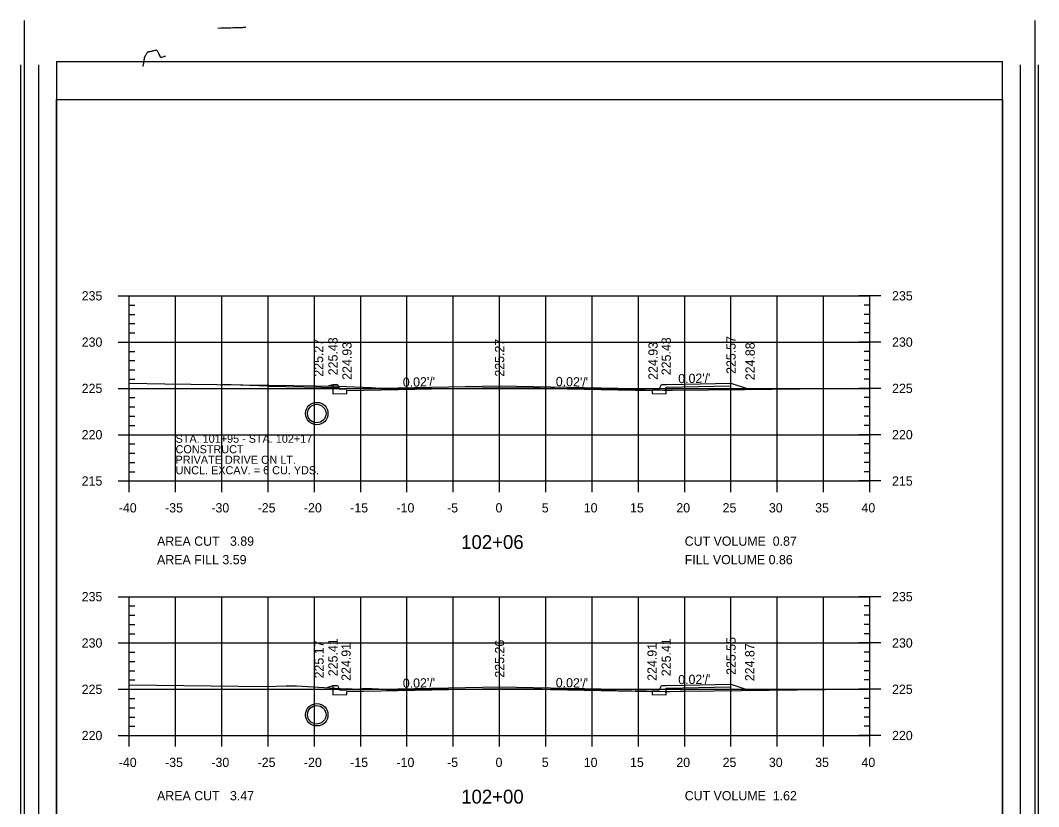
# Model space of a CAD drawing. Extents: x 1367903 to 1373764, y 376865 to 382130.
# Drawn here: x 1369975.7 to 1370195.7, y 377450.5 to 377620.4 of the extents above; entities that cross this region are included whole.
import ezdxf

# ---------------------------------------------------------------- set-up
doc = ezdxf.new("R2010")
doc.units = 0
for name, color, linetype in [('R_Axis', 7, 'Continuous'), ('R_Axis Annot', 7, 'Continuous'), ('R_Border', 7, 'Continuous'), ('R_Border PE', 7, 'Continuous'), ('R_Draft', 7, 'Continuous'), ('R_Drive', 7, 'Continuous'), ('R_Exist Surface', 7, 'Continuous'), ('R_Fin Surface', 7, 'Continuous'), ('R_Fin Surface Annot', 7, 'Continuous'), ('R_Grid', 7, 'Continuous'), ('R_Water', 7, 'Continuous')]:
    doc.layers.add(name, color=color, linetype=linetype)

msp = doc.modelspace()

# ---------------------------------------------------------------- linework, layer by layer
for points in [[(1370043.22, 377541.69), (1370043.22, 377541.03), (1370043.22, 377541.03), (1370043.22, 377539.66), (1370046.22, 377539.72), (1370046.22, 377540.39), (1370079.22, 377541.05), (1370112.22, 377540.39), (1370112.22, 377539.72), (1370115.22, 377539.66), (1370115.22, 377541.11), (1370129.22, 377541.39), (1370129.22, 377541.97)], [(1370043.22, 377476.66), (1370043.22, 377475.99), (1370043.22, 377475.99), (1370043.22, 377474.63), (1370046.22, 377474.69), (1370046.22, 377475.35), (1370079.22, 377476.01), (1370112.22, 377475.35), (1370112.22, 377474.69), (1370115.22, 377474.63), (1370115.22, 377476.07), (1370129.22, 377476.35), (1370129.22, 377476.94)]]:
    msp.add_lwpolyline(points)
at = {"layer": 'R_Axis'}
for p, q in [((1369996.82, 377560.84), (1370001.62, 377560.84)), ((1369999.22, 377520.84), (1369999.22, 377560.84)), ((1370161.62, 377560.84), (1370156.82, 377560.84)), ((1370159.22, 377520.84), (1370159.22, 377560.84)), ((1369999.22, 377558.84), (1370000.42, 377558.84)), ((1370159.22, 377558.84), (1370158.02, 377558.84)), ((1369999.22, 377556.84), (1370000.42, 377556.84)), ((1370159.22, 377556.84), (1370158.02, 377556.84)), ((1369999.22, 377554.84), (1370000.42, 377554.84)), ((1370159.22, 377554.84), (1370158.02, 377554.84)), ((1369999.22, 377552.84), (1370000.42, 377552.84)), ((1370159.22, 377552.84), (1370158.02, 377552.84)), ((1369996.82, 377550.84), (1370001.62, 377550.84)), ((1370161.62, 377550.84), (1370156.82, 377550.84)), ((1369999.22, 377548.84), (1370000.42, 377548.84)), ((1370159.22, 377548.84), (1370158.02, 377548.84)), ((1369999.22, 377546.84), (1370000.42, 377546.84)), ((1369999.22, 377544.84), (1370000.42, 377544.84)), ((1370159.22, 377546.84), (1370158.02, 377546.84)), ((1370159.22, 377544.84), (1370158.02, 377544.84)), ((1369999.22, 377542.84), (1370000.42, 377542.84)), ((1370159.22, 377542.84), (1370158.02, 377542.84)), ((1369996.82, 377540.84), (1370001.62, 377540.84)), ((1370161.62, 377540.84), (1370156.82, 377540.84)), ((1369999.22, 377538.84), (1370000.42, 377538.84)), ((1370159.22, 377538.84), (1370158.02, 377538.84)), ((1369999.22, 377536.84), (1370000.42, 377536.84)), ((1370159.22, 377536.84), (1370158.02, 377536.84)), ((1369999.22, 377534.84), (1370000.42, 377534.84)), ((1370159.22, 377534.84), (1370158.02, 377534.84)), ((1369999.22, 377532.84), (1370000.42, 377532.84)), ((1370159.22, 377532.84), (1370158.02, 377532.84)), ((1369996.82, 377530.84), (1370001.62, 377530.84)), ((1370161.62, 377530.84), (1370156.82, 377530.84)), ((1369999.22, 377528.84), (1370000.42, 377528.84)), ((1370159.22, 377528.84), (1370158.02, 377528.84)), ((1369999.22, 377526.84), (1370000.42, 377526.84)), ((1370159.22, 377526.84), (1370158.02, 377526.84)), ((1369999.22, 377524.84), (1370000.42, 377524.84)), ((1369999.22, 377518.44), (1369999.22, 377523.24)), ((1369999.22, 377522.84), (1370000.42, 377522.84)), ((1370009.22, 377518.44), (1370009.22, 377523.24)), ((1370019.22, 377518.44), (1370019.22, 377523.24)), ((1370029.22, 377518.44), (1370029.22, 377523.24)), ((1370039.22, 377518.44), (1370039.22, 377523.24)), ((1370049.22, 377518.44), (1370049.22, 377523.24)), ((1370059.22, 377518.44), (1370059.22, 377523.24)), ((1370069.22, 377518.44), (1370069.22, 377523.24)), ((1370079.22, 377518.44), (1370079.22, 377523.24)), ((1370089.22, 377518.44), (1370089.22, 377523.24)), ((1370099.22, 377518.44), (1370099.22, 377523.24)), ((1370109.22, 377518.44), (1370109.22, 377523.24)), ((1370119.22, 377518.44), (1370119.22, 377523.24)), ((1370129.22, 377518.44), (1370129.22, 377523.24)), ((1370139.22, 377518.44), (1370139.22, 377523.24)), ((1370149.22, 377518.44), (1370149.22, 377523.24)), ((1370159.22, 377524.84), (1370158.02, 377524.84)), ((1370159.22, 377522.84), (1370158.02, 377522.84)), ((1370159.22, 377518.44), (1370159.22, 377523.24)), ((1369996.82, 377520.84), (1370001.62, 377520.84)), ((1369999.22, 377520.84), (1370159.22, 377520.84)), ((1370161.62, 377520.84), (1370156.82, 377520.84)), ((1369996.82, 377495.84), (1370001.62, 377495.84)), ((1369999.22, 377465.84), (1369999.22, 377495.84)), ((1370161.62, 377495.84), (1370156.82, 377495.84)), ((1370159.22, 377465.84), (1370159.22, 377495.84)), ((1369999.22, 377493.84), (1370000.42, 377493.84)), ((1370159.22, 377493.84), (1370158.02, 377493.84)), ((1369999.22, 377491.84), (1370000.42, 377491.84)), ((1369999.22, 377489.84), (1370000.42, 377489.84)), ((1370159.22, 377491.84), (1370158.02, 377491.84)), ((1370159.22, 377489.84), (1370158.02, 377489.84)), ((1369999.22, 377487.84), (1370000.42, 377487.84)), ((1370159.22, 377487.84), (1370158.02, 377487.84)), ((1369996.82, 377485.84), (1370001.62, 377485.84)), ((1370161.62, 377485.84), (1370156.82, 377485.84)), ((1369999.22, 377483.84), (1370000.42, 377483.84)), ((1370159.22, 377483.84), (1370158.02, 377483.84)), ((1369999.22, 377481.84), (1370000.42, 377481.84)), ((1370159.22, 377481.84), (1370158.02, 377481.84)), ((1369999.22, 377479.84), (1370000.42, 377479.84)), ((1370159.22, 377479.84), (1370158.02, 377479.84)), ((1369999.22, 377477.84), (1370000.42, 377477.84)), ((1370159.22, 377477.84), (1370158.02, 377477.84)), ((1369996.82, 377475.84), (1370001.62, 377475.84)), ((1370161.62, 377475.84), (1370156.82, 377475.84)), ((1369999.22, 377473.84), (1370000.42, 377473.84)), ((1370159.22, 377473.84), (1370158.02, 377473.84)), ((1369999.22, 377471.84), (1370000.42, 377471.84)), ((1370159.22, 377471.84), (1370158.02, 377471.84)), ((1369999.22, 377469.84), (1370000.42, 377469.84)), ((1369999.22, 377463.44), (1369999.22, 377468.24)), ((1369999.22, 377467.84), (1370000.42, 377467.84)), ((1370009.22, 377463.44), (1370009.22, 377468.24)), ((1370019.22, 377463.44), (1370019.22, 377468.24)), ((1370029.22, 377463.44), (1370029.22, 377468.24)), ((1370039.22, 377463.44), (1370039.22, 377468.24)), ((1370049.22, 377463.44), (1370049.22, 377468.24)), ((1370059.22, 377463.44), (1370059.22, 377468.24)), ((1370069.22, 377463.44), (1370069.22, 377468.24)), ((1370079.22, 377463.44), (1370079.22, 377468.24)), ((1370089.22, 377463.44), (1370089.22, 377468.24)), ((1370099.22, 377463.44), (1370099.22, 377468.24)), ((1370109.22, 377463.44), (1370109.22, 377468.24)), ((1370119.22, 377463.44), (1370119.22, 377468.24)), ((1370129.22, 377463.44), (1370129.22, 377468.24)), ((1370139.22, 377463.44), (1370139.22, 377468.24)), ((1370149.22, 377463.44), (1370149.22, 377468.24)), ((1370159.22, 377469.84), (1370158.02, 377469.84)), ((1370159.22, 377467.84), (1370158.02, 377467.84)), ((1370159.22, 377463.44), (1370159.22, 377468.24)), ((1369996.82, 377465.84), (1370001.62, 377465.84)), ((1369999.22, 377465.84), (1370159.22, 377465.84)), ((1370161.62, 377465.84), (1370156.82, 377465.84))]:
    msp.add_line(p, q, dxfattribs=at)
at = {"layer": 'R_Border'}
for p, q in [((1369976.49, 377620.35), (1369976.49, 377279.12)), ((1370194.89, 377620.35), (1370194.89, 377279.12)), ((1369983.52, 377611.47), (1370187.85, 377611.47)), ((1369983.52, 377611.47), (1369983.52, 377280.59)), ((1370187.85, 377280.59), (1370187.85, 377611.47))]:
    msp.add_line(p, q, dxfattribs=at)
at = {"layer": 'R_Border PE'}
for p, q in [((1369975.69, 377610.76), (1369975.69, 377288.8)), ((1369979.6, 377610.76), (1369979.6, 377288.8)), ((1370191.77, 377288.8), (1370191.77, 377610.76)), ((1370195.69, 377288.8), (1370195.69, 377610.76)), ((1369983.52, 377603.25), (1370187.85, 377603.25)), ((1369983.52, 377288.8), (1369983.52, 377603.25)), ((1370187.85, 377603.25), (1370187.85, 377288.8))]:
    msp.add_line(p, q, dxfattribs=at)
for points in [[(1370020.38, 377618.69), (1370020.33, 377618.69), (1370020.05, 377618.68), (1370019.92, 377618.68), (1370019.85, 377618.67), (1370019.69, 377618.67), (1370019.34, 377618.66), (1370019.01, 377618.65), (1370018.37, 377618.63)], [(1370020.83, 377618.7), (1370020.38, 377618.69)], [(1370024.4, 377618.79), (1370024.05, 377618.78), (1370023.85, 377618.78), (1370023.69, 377618.77), (1370023.46, 377618.76), (1370023.3, 377618.76), (1370023.11, 377618.75), (1370022.86, 377618.75), (1370022.67, 377618.74), (1370022.39, 377618.73), (1370022.29, 377618.73), (1370022.24, 377618.73), (1370022.02, 377618.72), (1370021.91, 377618.72), (1370021.69, 377618.71), (1370021.61, 377618.72), (1370021.19, 377618.7), (1370020.95, 377618.7), (1370020.83, 377618.7)], [(1370007.08, 377612.54), (1370007.06, 377612.55), (1370007.04, 377612.55), (1370007.02, 377612.55), (1370007, 377612.55), (1370006.97, 377612.55), (1370006.94, 377612.55), (1370006.92, 377612.55), (1370006.78, 377612.51), (1370006.66, 377612.48), (1370006.39, 377612.41), (1370006.18, 377612.36), (1370006.15, 377612.35), (1370006.13, 377612.35), (1370006.11, 377612.34), (1370006.1, 377612.34), (1370006.09, 377612.35), (1370006.06, 377612.35), (1370006.04, 377612.36), (1370006.01, 377612.38), (1370006, 377612.39), (1370005.98, 377612.4), (1370005.96, 377612.42), (1370005.94, 377612.45), (1370005.93, 377612.47), (1370005.91, 377612.5), (1370005.89, 377612.55), (1370005.8, 377612.76), (1370005.69, 377613), (1370005.58, 377613.23), (1370005.57, 377613.26), (1370005.56, 377613.28), (1370005.52, 377613.34), (1370005.49, 377613.39), (1370005.37, 377613.57), (1370005.29, 377613.69), (1370005.26, 377613.74), (1370005.24, 377613.76), (1370005.23, 377613.78), (1370005.2, 377613.81), (1370005.19, 377613.83), (1370005.17, 377613.84), (1370005.16, 377613.85), (1370005.13, 377613.87), (1370005.12, 377613.87), (1370005.09, 377613.88), (1370005.06, 377613.88), (1370005.05, 377613.88), (1370005.01, 377613.88), (1370004.91, 377613.86), (1370004.74, 377613.82), (1370004.54, 377613.77), (1370004.4, 377613.74), (1370004.29, 377613.72), (1370004.15, 377613.69), (1370004.03, 377613.66), (1370003.85, 377613.63), (1370003.63, 377613.58), (1370003.59, 377613.57), (1370003.46, 377613.54), (1370003.35, 377613.52), (1370003.31, 377613.51), (1370003.28, 377613.5), (1370003.26, 377613.5), (1370003.24, 377613.49), (1370003.23, 377613.49), (1370003.21, 377613.47), (1370003.19, 377613.46), (1370003.17, 377613.44), (1370003.14, 377613.42), (1370003.11, 377613.39), (1370003.09, 377613.35), (1370003.06, 377613.31), (1370003.02, 377613.26), (1370002.96, 377613.16), (1370002.87, 377613.02), (1370002.78, 377612.89), (1370002.69, 377612.75), (1370002.64, 377612.67), (1370002.6, 377612.62), (1370002.56, 377612.55), (1370002.55, 377612.54), (1370002.54, 377612.52), (1370002.54, 377612.5), (1370002.53, 377612.48), (1370002.52, 377612.46), (1370002.52, 377612.44), (1370002.51, 377612.42), (1370002.5, 377612.39), (1370002.5, 377612.37), (1370002.49, 377612.35), (1370002.49, 377612.33), (1370002.47, 377612.24), (1370002.43, 377612), (1370002.39, 377611.76), (1370002.37, 377611.65), (1370002.28, 377611.18), (1370002.26, 377611.04), (1370002.22, 377610.84), (1370002.17, 377610.54), (1370002.14, 377610.39)]]:
    msp.add_lwpolyline(points, dxfattribs=at)
at = {"layer": 'R_Drive'}
for q in [(1370019.22, 377541.68), (1370044.55, 377541.03)]:
    msp.add_line((1370029.22, 377541.34), q, dxfattribs=at)
at = {"layer": 'R_Exist Surface'}
for points in [[(1369999.22, 377541.96), (1370006.92, 377541.84), (1370029.38, 377541.54), (1370034.79, 377541.45), (1370044.26, 377541.35), (1370051.48, 377541), (1370055.57, 377540.71), (1370056.7, 377540.69), (1370080.32, 377540.96), (1370084.92, 377541.03), (1370091.13, 377540.92), (1370114.68, 377540.44), (1370115.97, 377540.44), (1370116.56, 377540.44), (1370132.16, 377540.58), (1370156.06, 377540.89), (1370159.22, 377540.85)], [(1369999.22, 377476.81), (1370028.69, 377476.42), (1370033.08, 377476.58), (1370035.32, 377476.55), (1370046.09, 377475.94), (1370046.32, 377475.99), (1370048.48, 377475.89), (1370050.2, 377476.04), (1370053.09, 377475.95), (1370055.59, 377475.74), (1370056.75, 377475.66), (1370056.78, 377475.66), (1370058.74, 377475.68), (1370085.08, 377475.98), (1370110.96, 377475.45), (1370114.95, 377475.38), (1370116.03, 377475.36), (1370116.07, 377475.37), (1370118.24, 377475.39), (1370119.42, 377475.41), (1370155.6, 377475.87), (1370159.22, 377475.83)]]:
    msp.add_lwpolyline(points, dxfattribs=at)
at = {"layer": 'R_Fin Surface'}
for points in [[(1370042.26, 377541.37), (1370043.22, 377541.69), (1370044.22, 377541.69), (1370044.72, 377540.69), (1370046.22, 377540.72), (1370068.22, 377541.16), (1370079.22, 377541.38), (1370090.22, 377541.16), (1370112.22, 377540.72), (1370113.72, 377540.69), (1370114.22, 377541.69), (1370115.22, 377541.69), (1370119.22, 377541.77), (1370129.22, 377541.97), (1370133.35, 377540.6)], [(1370041.8, 377476.18), (1370043.22, 377476.66), (1370044.22, 377476.66), (1370044.72, 377475.66), (1370046.22, 377475.69), (1370068.22, 377476.13), (1370079.22, 377476.35), (1370090.22, 377476.13), (1370112.22, 377475.69), (1370113.72, 377475.66), (1370114.22, 377476.66), (1370115.22, 377476.66), (1370119.22, 377476.74), (1370129.22, 377476.94), (1370133.28, 377475.58)]]:
    msp.add_lwpolyline(points, dxfattribs=at)
at = {"layer": 'R_Grid'}
for p, q in [((1369999.22, 377560.84), (1370159.22, 377560.84)), ((1369999.22, 377520.84), (1369999.22, 377560.84)), ((1370009.22, 377520.84), (1370009.22, 377560.84)), ((1370019.22, 377520.84), (1370019.22, 377560.84)), ((1370029.22, 377520.84), (1370029.22, 377560.84)), ((1370039.22, 377520.84), (1370039.22, 377560.84)), ((1370049.22, 377520.84), (1370049.22, 377560.84)), ((1370059.22, 377520.84), (1370059.22, 377560.84)), ((1370069.22, 377520.84), (1370069.22, 377560.84)), ((1370079.22, 377520.84), (1370079.22, 377560.84)), ((1370089.22, 377520.84), (1370089.22, 377560.84)), ((1370099.22, 377520.84), (1370099.22, 377560.84)), ((1370109.22, 377520.84), (1370109.22, 377560.84)), ((1370119.22, 377520.84), (1370119.22, 377560.84)), ((1370129.22, 377520.84), (1370129.22, 377560.84)), ((1370139.22, 377520.84), (1370139.22, 377560.84)), ((1370149.22, 377520.84), (1370149.22, 377560.84)), ((1370159.22, 377520.84), (1370159.22, 377560.84)), ((1369999.22, 377550.84), (1370159.22, 377550.84)), ((1369999.22, 377540.84), (1370159.22, 377540.84)), ((1369999.22, 377530.84), (1370159.22, 377530.84)), ((1369999.22, 377520.84), (1370159.22, 377520.84)), ((1369999.22, 377495.84), (1370159.22, 377495.84)), ((1369999.22, 377465.84), (1369999.22, 377495.84)), ((1370009.22, 377465.84), (1370009.22, 377495.84)), ((1370019.22, 377465.84), (1370019.22, 377495.84)), ((1370029.22, 377465.84), (1370029.22, 377495.84)), ((1370039.22, 377465.84), (1370039.22, 377495.84)), ((1370049.22, 377465.84), (1370049.22, 377495.84)), ((1370059.22, 377465.84), (1370059.22, 377495.84)), ((1370069.22, 377465.84), (1370069.22, 377495.84)), ((1370079.22, 377465.84), (1370079.22, 377495.84)), ((1370089.22, 377465.84), (1370089.22, 377495.84)), ((1370099.22, 377465.84), (1370099.22, 377495.84)), ((1370109.22, 377465.84), (1370109.22, 377495.84)), ((1370119.22, 377465.84), (1370119.22, 377495.84)), ((1370129.22, 377465.84), (1370129.22, 377495.84)), ((1370139.22, 377465.84), (1370139.22, 377495.84)), ((1370149.22, 377465.84), (1370149.22, 377495.84)), ((1370159.22, 377465.84), (1370159.22, 377495.84)), ((1369999.22, 377485.84), (1370159.22, 377485.84)), ((1369999.22, 377475.84), (1370159.22, 377475.84)), ((1369999.22, 377465.84), (1370159.22, 377465.84))]:
    msp.add_line(p, q, dxfattribs=at)
at = {"layer": 'R_Water'}
for p, q in [((1370039.73, 377537.84), (1370039.73, 377537.8)), ((1370039.73, 377537.43), (1370039.73, 377537.38)), ((1370039.73, 377533.43), (1370039.73, 377533.38)), ((1370039.73, 377533.01), (1370039.73, 377532.96)), ((1370039.73, 377472.77), (1370039.73, 377472.72)), ((1370039.73, 377472.35), (1370039.73, 377472.3)), ((1370039.73, 377468.35), (1370039.73, 377468.3)), ((1370039.73, 377467.93), (1370039.73, 377467.89))]:
    msp.add_line(p, q, dxfattribs=at)
for centre, radius in [((1370039.73, 377535.4), 2.42), ((1370039.73, 377535.4), 2), ((1370039.73, 377470.33), 2.42), ((1370039.73, 377470.33), 2)]:
    msp.add_circle(centre, radius, dxfattribs=at)

# ---------------------------------------------------------------- texts
at = {"layer": 'R_Axis Annot'}
for s, height, p in [('235', 2, (1369988.94, 377559.84)), ('235', 2, (1370164.02, 377559.84)), ('230', 2, (1369988.94, 377549.84)), ('230', 2, (1370164.02, 377549.84)), ('225', 2, (1369988.94, 377539.84)), ('225', 2, (1370164.02, 377539.84)), ('220', 2, (1369988.94, 377529.84)), ('220', 2, (1370164.02, 377529.84)), ('215', 2, (1369988.94, 377519.84)), ('215', 2, (1370164.02, 377519.84)), ('-40', 2, (1369996.95, 377514.04)), ('-35', 2, (1370006.95, 377514.04)), ('-30', 2, (1370016.95, 377514.04)), ('-25', 2, (1370026.95, 377514.04)), ('-20', 2, (1370036.95, 377514.04)), ('-15', 2, (1370046.95, 377514.04)), ('-10', 2, (1370056.95, 377514.04)), ('-5', 2, (1370067.88, 377514.04)), ('0', 2, (1370078.35, 377514.04)), ('5', 2, (1370088.34, 377514.04)), ('10', 2, (1370097.41, 377514.04)), ('15', 2, (1370107.41, 377514.04)), ('20', 2, (1370117.41, 377514.04)), ('25', 2, (1370127.41, 377514.04)), ('30', 2, (1370137.41, 377514.04)), ('35', 2, (1370147.41, 377514.04)), ('40', 2, (1370157.41, 377514.04)), ('AREA CUT   3.89', 2, (1370005.22, 377506.84)), ('102+06', 3, (1370070.92, 377506.14)), ('CUT VOLUME  0.87', 2, (1370119.22, 377506.84)), ('AREA FILL 3.59', 2, (1370005.22, 377502.84)), ('FILL VOLUME 0.86', 2, (1370119.22, 377502.84)), ('235', 2, (1369988.94, 377494.84)), ('235', 2, (1370164.02, 377494.84)), ('230', 2, (1369988.94, 377484.84)), ('230', 2, (1370164.02, 377484.84)), ('225', 2, (1369988.94, 377474.84)), ('225', 2, (1370164.02, 377474.84)), ('220', 2, (1369988.94, 377464.84)), ('220', 2, (1370164.02, 377464.84)), ('-40', 2, (1369996.95, 377459.04)), ('-35', 2, (1370006.95, 377459.04)), ('-30', 2, (1370016.95, 377459.04)), ('-25', 2, (1370026.95, 377459.04)), ('-20', 2, (1370036.95, 377459.04)), ('-15', 2, (1370046.95, 377459.04)), ('-10', 2, (1370056.95, 377459.04)), ('-5', 2, (1370067.88, 377459.04)), ('0', 2, (1370078.35, 377459.04)), ('5', 2, (1370088.34, 377459.04)), ('10', 2, (1370097.41, 377459.04)), ('15', 2, (1370107.41, 377459.04)), ('20', 2, (1370117.41, 377459.04)), ('25', 2, (1370127.41, 377459.04)), ('30', 2, (1370137.41, 377459.04)), ('35', 2, (1370147.41, 377459.04)), ('40', 2, (1370157.41, 377459.04)), ('AREA CUT   3.47', 2, (1370005.22, 377451.84)), ('102+00', 3, (1370070.93, 377451.14)), ('CUT VOLUME  1.62', 2, (1370119.22, 377451.84))]:
    msp.add_text(s, height=height, dxfattribs=at).set_placement(p)
at = {"layer": 'R_Draft'}
for s, p in [('STA. 101+95 - STA. 102+17', (1370009.22, 377529.09)), ('CONSTRUCT', (1370009.22, 377526.82)), ('PRIVATE DRIVE ON LT.', (1370009.22, 377524.55)), ('UNCL. EXCAV. = 6 CU. YDS.', (1370009.22, 377522.28))]:
    msp.add_text(s, height=1.75, dxfattribs=at).set_placement(p)
at = {"layer": 'R_Fin Surface Annot'}
for s, rotation, p in [('225.27', 90, (1370041.11, 377543.37)), ('225.43', 90, (1370044.22, 377543.69)), ('225.27', 90, (1370080.22, 377543.38)), ('225.43', 90, (1370116.22, 377543.69)), ('225.57', 90, (1370130.22, 377543.97)), ('224.93', 90, (1370047.25, 377542.69)), ('224.93', 90, (1370113.38, 377542.69)), ('224.88', 90, (1370134.35, 377542.6)), ("0.02'/'", 1.1458, (1370058.34, 377541.17)), ("0.02'/'", 358.8542, (1370091.35, 377541.34)), ("0.02'/'", 1.1458, (1370117.84, 377541.95)), ('225.17', 90, (1370041.22, 377478.18)), ('225.41', 90, (1370044.22, 377478.66)), ('224.91', 90, (1370047.06, 377477.66)), ('225.26', 90, (1370080.22, 377478.35)), ('224.91', 90, (1370113.17, 377477.66)), ('225.41', 90, (1370116.22, 377478.66)), ('225.55', 90, (1370130.22, 377478.94)), ('224.87', 90, (1370134.28, 377477.58)), ("0.02'/'", 1.1458, (1370117.84, 377476.91)), ("0.02'/'", 1.1458, (1370058.34, 377476.13)), ("0.02'/'", 358.8542, (1370091.35, 377476.3))]:
    msp.add_text(s, height=2, rotation=rotation, dxfattribs=at).set_placement(p)

doc.saveas('drawing.dxf')
